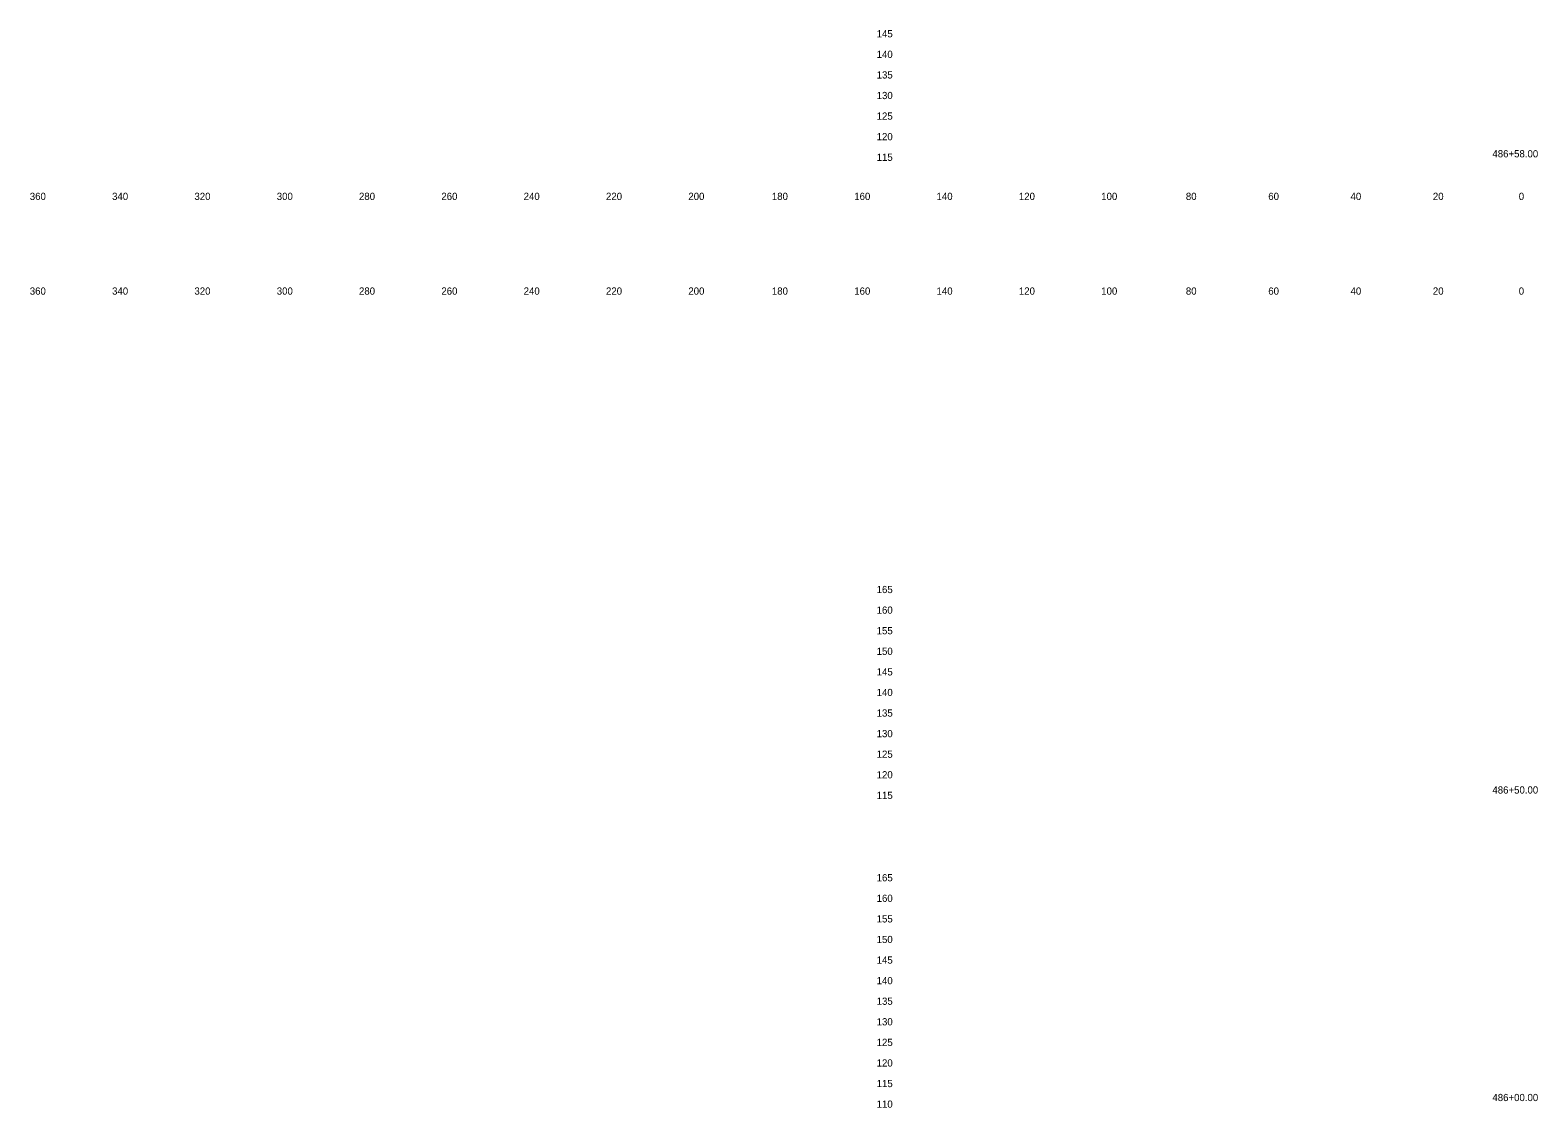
# Model space of a CAD drawing. Extents: x 21281 to 22024, y 6472 to 15198.
# Drawn here: x 21280.5 to 21646.7, y 13844.8 to 14106.6 of the extents above; entities that cross this region are included whole.
import ezdxf

# ---------------------------------------------------------------- set-up
doc = ezdxf.new("R2010")
doc.units = 0
for name, color, linetype in [('Draft_XS_Grid', 7, 'Continuous'), ('Draft_XS_Text', 7, 'Continuous'), ('SLOPE_STAKES_FILL', 7, 'Continuous')]:
    doc.layers.add(name, color=color, linetype=linetype)

msp = doc.modelspace()

# ---------------------------------------------------------------- texts
at = {"layer": 'Draft_XS_Grid'}
for s, p in [('  145  ', (21484.84, 14104.84)), ('  140  ', (21484.84, 14099.84)), ('  135  ', (21484.84, 14094.84)), ('  130  ', (21484.84, 14089.84)), ('  125  ', (21484.84, 14084.84)), ('  120  ', (21484.84, 14079.84)), ('  115  ', (21484.84, 14074.84)), ('  165  ', (21484.84, 13969.84)), ('  160  ', (21484.84, 13964.84)), ('  155  ', (21484.84, 13959.84)), ('  150  ', (21484.84, 13954.84)), ('  145  ', (21484.84, 13949.84)), ('  140  ', (21484.84, 13944.84)), ('  135  ', (21484.84, 13939.84)), ('  130  ', (21484.84, 13934.84)), ('  125  ', (21484.84, 13929.84)), ('  120  ', (21484.84, 13924.84)), ('  115  ', (21484.84, 13919.84)), ('  165  ', (21484.84, 13899.84)), ('  160  ', (21484.84, 13894.84)), ('  155  ', (21484.84, 13889.84)), ('  150  ', (21484.84, 13884.84)), ('  145  ', (21484.84, 13879.84)), ('  140  ', (21484.84, 13874.84)), ('  135  ', (21484.84, 13869.84)), ('  130  ', (21484.84, 13864.84)), ('  125  ', (21484.84, 13859.84)), ('  120  ', (21484.84, 13854.84)), ('  115  ', (21484.84, 13849.84)), ('  110  ', (21484.84, 13844.84))]:
    msp.add_text(s, height=1.75, dxfattribs=at).set_placement(p)
at = {"layer": 'Draft_XS_Text'}
for s, p in [('  360  ', (21279.14, 14065.34)), ('  340  ', (21299.13, 14065.34)), ('  320  ', (21319.13, 14065.34)), ('  300  ', (21339.13, 14065.34)), ('  280  ', (21359.1, 14065.34)), ('  260  ', (21379.11, 14065.34)), ('  240  ', (21399.1, 14065.34)), ('  220  ', (21419.1, 14065.34)), ('  200  ', (21439.1, 14065.34)), ('  180  ', (21459.39, 14065.34)), ('  160  ', (21479.4, 14065.34)), ('  140  ', (21499.39, 14065.34)), ('  120  ', (21519.39, 14065.34)), ('  100  ', (21539.39, 14065.34)), ('  80  ', (21559.95, 14065.34)), ('  60  ', (21579.97, 14065.34)), ('  40  ', (21599.95, 14065.34)), ('  20  ', (21619.95, 14065.34)), ('  0  ', (21640.81, 14065.34)), ('  0  ', (21640.81, 14065.34)), ('  360  ', (21279.14, 14042.34)), ('  340  ', (21299.13, 14042.34)), ('  320  ', (21319.13, 14042.34)), ('  300  ', (21339.13, 14042.34)), ('  280  ', (21359.1, 14042.34)), ('  260  ', (21379.11, 14042.34)), ('  240  ', (21399.1, 14042.34)), ('  220  ', (21419.1, 14042.34)), ('  200  ', (21439.1, 14042.34)), ('  180  ', (21459.39, 14042.34)), ('  160  ', (21479.4, 14042.34)), ('  140  ', (21499.39, 14042.34)), ('  120  ', (21519.39, 14042.34)), ('  100  ', (21539.39, 14042.34)), ('  80  ', (21559.95, 14042.34)), ('  60  ', (21579.97, 14042.34)), ('  40  ', (21599.95, 14042.34)), ('  20  ', (21619.95, 14042.34)), ('  0  ', (21640.81, 14042.34)), ('  0  ', (21640.81, 14042.34))]:
    msp.add_text(s, height=1.75, dxfattribs=at).set_placement(p)
at = {"layer": 'SLOPE_STAKES_FILL'}
for s, p in [('  486+58.00  ', (21634.41, 14075.69)), ('  486+50.00  ', (21634.41, 13921.15)), ('  486+00.00  ', (21634.41, 13846.45))]:
    msp.add_text(s, height=1.75, dxfattribs=at).set_placement(p)

doc.saveas('drawing.dxf')
